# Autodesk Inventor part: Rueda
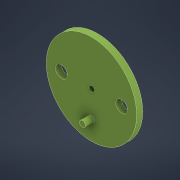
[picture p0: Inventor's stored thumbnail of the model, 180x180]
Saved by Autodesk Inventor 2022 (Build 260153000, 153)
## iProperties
Created: 2021-08
Part Number: Rueda
Material: Titanium
Document SubType Name: Modeling
Designer: user
Density: 4.51 g/cm^3
Appearance: Olive Green
Mass: 0.770417 g
Surface Area: 4.06836 cm^2
Volume: 0.170824 cm^3
Author: user
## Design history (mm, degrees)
sketch "Sketch1"
  geometry: C1 r 7.5 at (0, 0); C2 r 0.5 at (0, 0); 1 further point
  constraints: 2 centre point, 2 coincident
  dimensions: "d0" = 15 diameter of C1; "d3" = 1 diameter of C2
extrude "Extrusion1" new body sketch "Sketch1" distance "d1" = 1; taper "d2" = 0 deg
sketch "Sketch2"
  geometry: C1 r 0.5 at (0, -4.239); 1 further point
  constraints: 1 centre point
  dimensions: "d4" = 1 diameter of C1
extrude "Extrusion2" join sketch "Sketch2" distance "d5" = 1.5; taper "d6" = 0 deg
sketch "Sketch3"
  geometry: L1 (0, 0)-(0, 2.743); C1 r 1 at (5, 0); C2 r 0.5 at (0, 0) reference; C3 r 1 at (-5, 0); 1 further point
  constraints: 2 centre point, 2 end point, 1 symmetric about line, 1 vertical, 1 other
  dimensions: "d7" = 2 diameter of C1; "d8" = 5 distance of point (0, 0) C1.centre
extrude "Extrusion3" cut sketch "Sketch3" extent not by distance; stored distance "d9" = 0; taper "d10" = 0 deg
body "Solid1"
